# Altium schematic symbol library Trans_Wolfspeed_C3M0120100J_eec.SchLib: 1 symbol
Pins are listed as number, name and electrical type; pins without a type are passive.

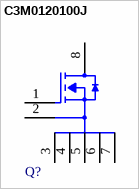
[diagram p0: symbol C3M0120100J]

## C3M0120100J
designator Q?  (value not drawn)
pins: 1 Gate, 2 Driver Source, 3 Power Source, 4 Power Source, 5 Power Source, 6 Power Source, 7 Power Source, 8 Drain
